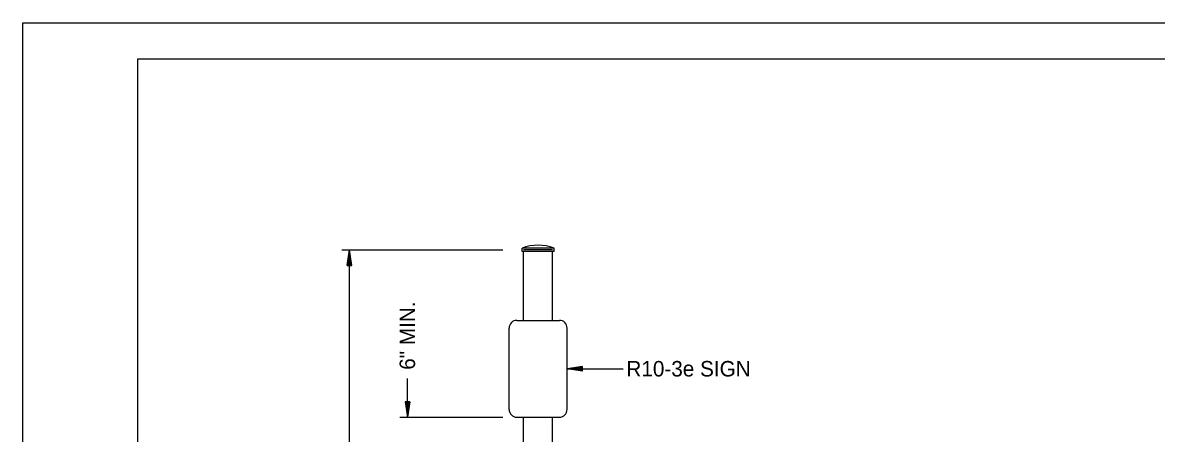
# Model space of a CAD drawing. Extents: x 1370140 to 1371141, y 380020 to 380660.
# Drawn here: x 1370140.5 to 1370506.7, y 380527.5 to 380660 of the extents above; entities that cross this region are included whole.
import ezdxf

# ---------------------------------------------------------------- set-up
doc = ezdxf.new("R2010")
doc.units = 0
for name, color, linetype in [('R_Border', 7, 'Continuous'), ('R_Draft', 7, 'Continuous'), ('R_No Plot', 7, 'Continuous')]:
    doc.layers.add(name, color=color, linetype=linetype)

msp = doc.modelspace()

# ---------------------------------------------------------------- linework, layer by layer
at = {"layer": 'R_Border'}
for p, q in [((1370177.71, 380648.36), (1371126.25, 380648.36)), ((1370177.71, 380031.98), (1370177.71, 380648.36))]:
    msp.add_line(p, q, dxfattribs=at)
at = {"layer": 'R_Draft'}
for p, q in [((1370243.53, 380586.73), (1370295.6, 380586.73)), ((1370245.28, 380581.73), (1370246.03, 380586.73)), ((1370245.41, 380581.73), (1370246.03, 380585.9)), ((1370246.03, 380432.73), (1370246.03, 380586.73)), ((1370246.78, 380581.73), (1370246.03, 380586.73)), ((1370246.66, 380581.73), (1370246.03, 380585.9)), ((1370312.16, 380587.23), (1370301.78, 380587.23)), ((1370301.78, 380586.23), (1370301.78, 380587.23)), ((1370312.16, 380586.23), (1370301.78, 380586.23)), ((1370311.66, 380586.73), (1370302.28, 380586.73)), ((1370302.28, 380563.98), (1370302.28, 380586.23)), ((1370311.66, 380563.98), (1370311.66, 380586.23)), ((1370312.16, 380586.23), (1370312.16, 380587.23)), ((1370245.54, 380581.73), (1370246.03, 380585.04)), ((1370245.66, 380581.73), (1370246.03, 380584.2)), ((1370245.79, 380581.73), (1370246.03, 380583.36)), ((1370245.92, 380581.73), (1370246.03, 380582.52)), ((1370246.53, 380581.73), (1370246.03, 380585.04)), ((1370246.41, 380581.73), (1370246.03, 380584.2)), ((1370246.28, 380581.73), (1370246.03, 380583.36)), ((1370246.15, 380581.73), (1370246.03, 380582.52)), ((1370245.28, 380581.73), (1370246.78, 380581.73)), ((1370300.1, 380563.98), (1370313.85, 380563.98)), ((1370297.6, 380535.23), (1370297.6, 380561.48)), ((1370316.35, 380535.23), (1370316.35, 380561.48)), ((1370321.35, 380549.11), (1370316.35, 380548.36)), ((1370316.35, 380548.36), (1370334.45, 380548.36)), ((1370321.35, 380547.61), (1370316.35, 380548.36)), ((1370321.35, 380548.98), (1370317.18, 380548.36)), ((1370321.35, 380547.73), (1370317.18, 380548.36)), ((1370321.35, 380548.86), (1370318.04, 380548.36)), ((1370321.35, 380547.86), (1370318.04, 380548.36)), ((1370321.35, 380548.73), (1370318.87, 380548.36)), ((1370321.35, 380547.99), (1370318.87, 380548.36)), ((1370321.35, 380548.6), (1370319.72, 380548.36)), ((1370321.35, 380548.12), (1370319.72, 380548.36)), ((1370321.35, 380548.48), (1370320.56, 380548.36)), ((1370321.35, 380548.24), (1370320.56, 380548.36)), ((1370321.35, 380547.61), (1370321.35, 380549.11)), ((1370264.78, 380532.73), (1370264.78, 380545.23)), ((1370264.03, 380537.73), (1370264.78, 380532.73)), ((1370265.53, 380537.73), (1370264.03, 380537.73)), ((1370264.16, 380537.73), (1370264.78, 380533.57)), ((1370264.29, 380537.73), (1370264.78, 380534.43)), ((1370264.41, 380537.73), (1370264.78, 380535.26)), ((1370264.54, 380537.73), (1370264.78, 380536.11)), ((1370264.67, 380537.73), (1370264.78, 380536.94)), ((1370265.53, 380537.73), (1370264.78, 380532.73)), ((1370265.03, 380537.73), (1370264.78, 380536.11)), ((1370265.28, 380537.73), (1370264.78, 380534.43)), ((1370265.41, 380537.73), (1370264.78, 380533.57)), ((1370265.16, 380537.73), (1370264.78, 380535.26)), ((1370264.9, 380537.73), (1370264.78, 380536.94)), ((1370262.28, 380532.73), (1370295.6, 380532.73)), ((1370300.1, 380532.73), (1370313.85, 380532.73)), ((1370302.28, 380436.73), (1370302.28, 380532.73)), ((1370311.66, 380436.73), (1370311.66, 380532.73))]:
    msp.add_line(p, q, dxfattribs=at)
for centre, radius, start, end in [((1370306.97, 380574.28), 13.96, 68.1777, 111.8223), ((1370300.1, 380561.48), 2.5, 90, 180), ((1370313.85, 380561.48), 2.5, 360, 90), ((1370300.1, 380535.23), 2.5, 180, 270), ((1370313.85, 380535.23), 2.5, 270, 0)]:
    msp.add_arc(centre, radius, start, end, dxfattribs=at)
at = {"layer": 'R_No Plot'}
msp.add_line((1370140.51, 380660.04), (1371140.51, 380660.04), dxfattribs=at)
msp.add_lwpolyline([(1370140.49, 380660.04), (1371140.51, 380660.04), (1371140.51, 380020.03), (1370140.49, 380020.03)], close=True, dxfattribs=at)

# ---------------------------------------------------------------- texts
at = {"layer": 'R_Draft'}
msp.add_text('6" MIN.', height=5, rotation=90, dxfattribs=at).set_placement((1370267.24, 380548.02))
msp.add_text('R10-3e SIGN', height=5, dxfattribs=at).set_placement((1370335.5, 380545.86))

doc.saveas('drawing.dxf')
